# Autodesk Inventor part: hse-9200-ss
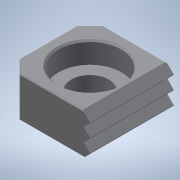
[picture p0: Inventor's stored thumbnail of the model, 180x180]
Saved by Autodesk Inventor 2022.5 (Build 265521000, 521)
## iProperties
Created: 2016-12
Part Number: hse-9200-ss
Material: 一般
Document SubType Name: Modeling
Designer: imaocorp
Density: 1 g/cm^3
Appearance: 既定
Author: imaocorp
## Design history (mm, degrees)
node "hse-9200-ss.x_t1"
node "hse-9200-ss"
node "Base1"
